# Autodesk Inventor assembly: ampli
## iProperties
Created: 2009-06
Part Number: ampli
Document SubType Name: Assembly
Designer: ajtco
Manufacturer: Standard
Standards Organization: Custom
Author: ajtco
